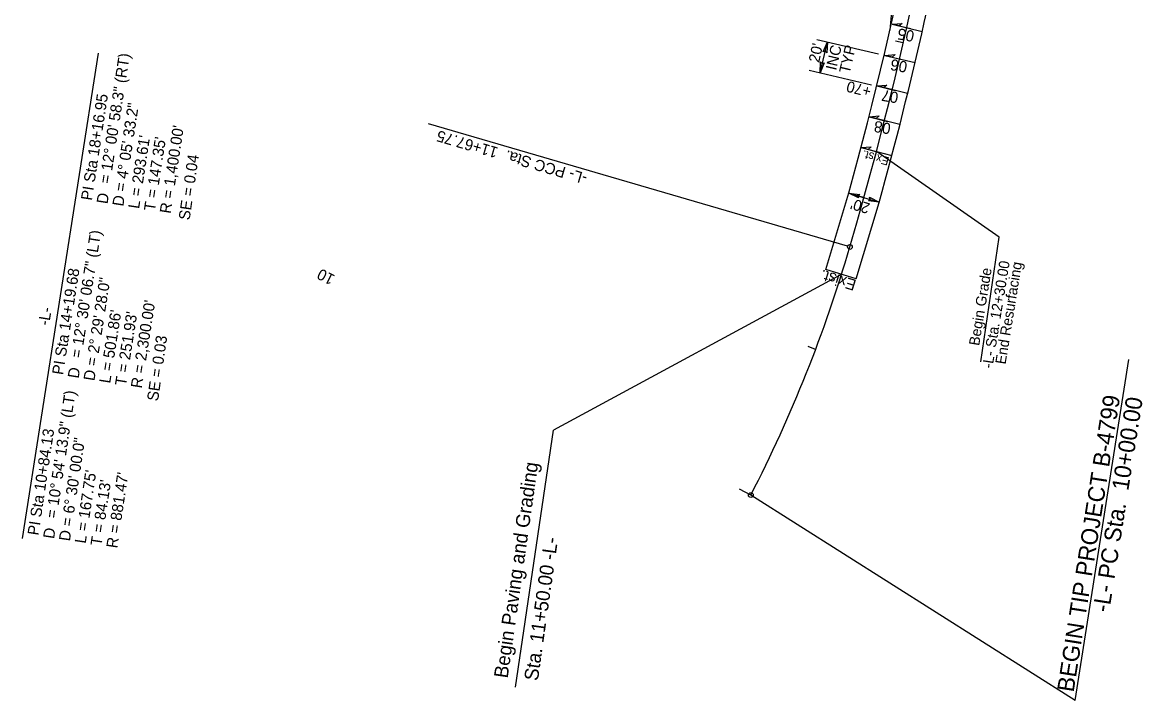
# Model space of a CAD drawing. Extents: x 1698814 to 1699654, y 708133 to 709468.
# Drawn here: x 1698814 to 1699516, y 708133 to 708558 of the extents above; entities that cross this region are included whole.
import ezdxf

# ---------------------------------------------------------------- set-up
doc = ezdxf.new("R2010")
doc.units = 0
for name, color, linetype in [('Prop Dimension', 7, 'Continuous'), ('Prop EOT', 7, 'Continuous'), ('Prop Horizontal Alignment', 7, 'Continuous'), ('Prop Horizontal Alignment Curve and Spiral Data', 7, 'Continuous'), ('Prop Horizontal Alignment Station Label', 7, 'Continuous'), ('Prop Horizontal Alignment Tick Label', 7, 'Continuous'), ('Prop Horizontal Alignment Tick Large', 7, 'Continuous'), ('Prop Horizontal Alignment Tick Small', 7, 'Continuous'), ('Prop Paved Shoulder', 7, 'Continuous'), ('Prop Superelevation  Arrow CELL', 7, 'Continuous'), ('Prop Superelevation Label', 7, 'Continuous'), ('Prop Terminator CELL', 7, 'Continuous')]:
    doc.layers.add(name, color=color, linetype=linetype)

msp = doc.modelspace()

# ---------------------------------------------------------------- linework, layer by layer
at = {"layer": 'Prop Dimension'}
for p, q in [((1699311.81, 708547.55), (1699350.41, 708538.5)), ((1699313.93, 708526.58), (1699318.48, 708545.99)), ((1699306.96, 708528.22), (1699346, 708519.06)), ((1699426.08, 708423.55), (1699349.17, 708477.19)), ((1699331.9, 708451.23), (1699350.97, 708445.54)), ((1699414.52, 708345.43), (1699426.08, 708423.55)), ((1699336.52, 708397.37), (1699317.59, 708403.33))]:
    msp.add_line(p, q, dxfattribs=at)
at = {"layer": 'Prop EOT'}
for p, q in [((1699317.59, 708403.33), (1699331.83, 708451.27)), ((1699336.52, 708397.37), (1699350.89, 708445.24))]:
    msp.add_line(p, q, dxfattribs=at)
for centre, radius, start, end in [((1697132.82, 709061.2), 2282.04, 344.49766, 353.61848), ((1697124.94, 709062.69), 2310, 344.49666, 350.26654)]:
    msp.add_arc(centre, radius, start, end, dxfattribs=at)
at = {"layer": 'Prop Horizontal Alignment'}
for centre, radius, start, end in [((1697124.94, 709062.69), 2300, 343.70663, 356.20849), ((1698486.49, 708664.71), 881.47, 332.80277, 343.70663)]:
    msp.add_arc(centre, radius, start, end, dxfattribs=at)
at = {"layer": 'Prop Horizontal Alignment Station Label'}
for p, q in [((1698814.22, 708234.64), (1698861.81, 708538.93)), ((1699331.12, 708417.83), (1699068.61, 708494.56)), ((1699327.41, 708400.42), (1699146.89, 708302.62)), ((1699473.71, 708132.99), (1699507.36, 708346.78)), ((1699123.05, 708141.38), (1699146.89, 708302.62)), ((1699473.71, 708132.99), (1699270.51, 708261.83))]:
    msp.add_line(p, q, dxfattribs=at)
for centre in [(1699332.56, 708417.41), (1699270.51, 708261.83)]:
    msp.add_circle(centre, 1.5, dxfattribs=at)
at = {"layer": 'Prop Horizontal Alignment Tick Large'}
msp.add_line((1699270.51, 708261.83), (1699263.39, 708265.49), dxfattribs=at)
at = {"layer": 'Prop Horizontal Alignment Tick Small'}
for p, q in [((1699366, 708545.34), (1699361.13, 708546.47)), ((1699341.39, 708448.42), (1699336.57, 708449.76)), ((1699311.08, 708353.17), (1699306.4, 708354.94))]:
    msp.add_line(p, q, dxfattribs=at)
at = {"layer": 'Prop Paved Shoulder'}
msp.add_line((1699361.34, 708597.31), (1699357.64, 708553.41), dxfattribs=at)
at = {"layer": 'Prop Superelevation  Arrow CELL'}
for p, q in [((1699358.95, 708557.04), (1699370.63, 708554.29)), ((1699354.53, 708537.53), (1699366.21, 708534.78)), ((1699349.38, 708518.49), (1699361.01, 708515.54)), ((1699344.54, 708499.09), (1699356.17, 708496.13)), ((1699339.53, 708479.73), (1699351.14, 708476.68))]:
    msp.add_line(p, q, dxfattribs=at)
for points in [[(1699358.95, 708557.04), (1699365.25, 708557.61), (1699363.45, 708555.98)], [(1699354.53, 708537.53), (1699360.83, 708538.11), (1699359.03, 708536.47)], [(1699349.38, 708518.49), (1699355.69, 708518.95), (1699353.87, 708517.35)], [(1699344.54, 708499.09), (1699350.85, 708499.55), (1699349.02, 708497.95)], [(1699339.53, 708479.73), (1699345.84, 708480.14), (1699344, 708478.56)]]:
    msp.add_lwpolyline(points, close=True, dxfattribs=at)
at = {"layer": 'Prop Superelevation Label'}
for p, q in [((1699358.95, 708557.04), (1699377.91, 708552.58)), ((1699354.53, 708537.53), (1699373.41, 708533.09)), ((1699368.72, 708513.58), (1699349.38, 708518.49)), ((1699363.89, 708494.17), (1699344.54, 708499.09)), ((1699339.53, 708479.73), (1699358.84, 708474.65))]:
    msp.add_line(p, q, dxfattribs=at)
at = {"layer": 'Prop Terminator CELL'}
for points in [[(1699315.76, 708539.7), (1699318.48, 708545.99), (1699318.04, 708539.11), (1699317.08, 708540.23)], [(1699316.53, 708532.92), (1699313.93, 708526.58), (1699314.24, 708533.47), (1699315.22, 708532.36)], [(1699338.02, 708448.15), (1699331.9, 708451.23), (1699338.74, 708450.4), (1699337.57, 708449.5)], [(1699344.87, 708448.65), (1699350.97, 708445.54), (1699344.13, 708446.4), (1699345.31, 708447.29)]]:
    msp.add_lwpolyline(points, close=True, dxfattribs=at)

# ---------------------------------------------------------------- texts
at = {"layer": 'Prop Dimension'}
for s, height, rotation, p in [("20'", 6.825, 77.70494, (1699313.27, 708532.59)), ('INC', 6.825, 76.7999, (1699323.92, 708527.76)), ('TYP', 6.825, 76.7999, (1699332.34, 708525.78)), ('+70', 6.825, 165.96125, (1699346.49, 708517.79)), ("20'", 6.825, 163.41691, (1699345.64, 708444.55)), ('-L- Sta. 12+30.00', 6.5625, 80.74773, (1699421.82, 708341)), ('End Resurfacing', 6.5625, 80.74773, (1699430.04, 708343.52)), ('Begin Grade', 6.5625, 80.74773, (1699413.53, 708355.17))]:
    msp.add_text(s, height=height, rotation=rotation, dxfattribs=at).set_placement(p)
at = {"layer": 'Prop Horizontal Alignment Curve and Spiral Data'}
for s, height, rotation, p in [('= 12%%d 00\' 58.3" (RT)', 7, 81.32299, (1698869.17, 708456.82)), ('PI Sta 18+16.95', 7, 81.32299, (1698857.74, 708446.24)), ('D = 4%%d 05\' 33.2"', 7, 81.32299, (1698877.41, 708442.56)), ("R = 1,400.00'", 7, 81.32299, (1698907.07, 708438.03)), ("L = 293.61'", 7, 81.32299, (1698887.3, 708441.05)), ("T = 147.35'", 7, 81.32299, (1698897.18, 708439.54)), ('SE = 0.04', 7, 81.82724, (1698918.94, 708433.92)), ('D', 7, 81.32299, (1698867.53, 708444.07)), ('= 12%%d 30\' 06.7" (LT)', 7, 81.1024, (1698851.12, 708347.43)), ('PI Sta 14+19.68', 7, 81.1024, (1698839.65, 708336.9)), ('D = 2%%d 29\' 28.0"', 7, 81.1024, (1698859.31, 708333.14)), ('-L-', 7, 80.52015, (1698830.86, 708367.77)), ("R = 2,300.00'", 7, 81.1024, (1698888.95, 708328.5)), ("L = 501.86'", 7, 81.1024, (1698869.19, 708331.59)), ("T = 251.93'", 7, 81.1024, (1698879.07, 708330.05)), ('SE = 0.03', 7, 81.91369, (1698899.17, 708320.44)), ('D', 7, 81.1024, (1698849.43, 708334.69)), ('= 10%%d 54\' 13.9" (LT)', 7, 81.52701, (1698835.66, 708246.89)), ('BEGIN TIP PROJECT B-4799', 10.5, 81.05462, (1699472.67, 708137.91)), ('PI Sta 10+84.13', 7, 81.52701, (1698824.27, 708236.28)), ('D = 6%%d 30\' 00.0"', 7, 81.52701, (1698843.95, 708232.66)), ('Begin Paving and Grading', 8.75, 81.91369, (1699118.18, 708146.71)), ("L = 167.75'", 7, 81.52701, (1698853.84, 708231.19)), ("R = 881.47'", 7, 81.52701, (1698873.62, 708228.24)), ("T = 84.13'", 7, 81.52701, (1698863.73, 708229.72)), ('D', 7, 81.52701, (1698834.06, 708234.14)), ('Sta. 11+50.00 -L-', 8.75, 81.91369, (1699137.11, 708145.04))]:
    msp.add_text(s, height=height, rotation=rotation, dxfattribs=at).set_placement(p)
at = {"layer": 'Prop Horizontal Alignment Station Label'}
for s, height, rotation, p in [('-L- PCC Sta.  11+67.75', 7, 163.70663, (1699168.6, 708463.25)), ('-L- PC Sta.  10+00.00', 10.5, 81.05462, (1699494.93, 708187.9))]:
    msp.add_text(s, height=height, rotation=rotation, dxfattribs=at).set_placement(p)
at = {"layer": 'Prop Horizontal Alignment Tick Label'}
msp.add_text('10', height=7, rotation=152.80277, dxfattribs=at).set_placement((1699010.49, 708399.38))
at = {"layer": 'Prop Superelevation Label'}
for s, height, rotation, p in [('05', 7, 170.12907, (1699373.29, 708552.79)), ('06', 7, 170.12907, (1699368.93, 708533.49)), ('07', 7, 170.12907, (1699363.37, 708514.25)), ('08', 7, 170.12907, (1699358.6, 708494.8)), ('Exist.', 5.25, 163.94325, (1699357.6, 708473.4)), ('Exist.', 7, 162.63368, (1699337.11, 708396.51))]:
    msp.add_text(s, height=height, rotation=rotation, dxfattribs=at).set_placement(p)

doc.saveas('drawing.dxf')
